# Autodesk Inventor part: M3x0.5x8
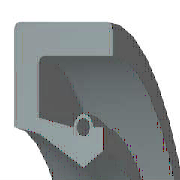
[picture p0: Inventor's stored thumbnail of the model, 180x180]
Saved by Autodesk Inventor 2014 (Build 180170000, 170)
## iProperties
Company: 한국ATC센터
IsCustomPart: 1
Created: 2009-02
Part Number: M3x0.5x8
Material: 고무
Description: 오일-실
Document SubType Name: Modeling
Standard: KS B 2804
Designer: KYOUNG IL JANG
Standards Organization: KS
Language: ko-KR
Size Designation: S - 12 22 7
Categories: <MemberInstance><Categories><Category DisplayName="샤프트 부품" InternalName="7f7aeb1f-a693-4053-b835-cee3144e0d98" Mnemonic="SHFT"><Category DisplayName="실링" Intern
Density: 0.93 g/cm^3
Mass: 1.0258 g
Surface Area: 17.5559 cm^2
Volume: 1.10301 cm^3
Vendor: CBT Solutions
Appearance: 고무 - 검은색 - 버전 1.1
Author: KYOUNG IL JANG
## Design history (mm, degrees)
revolve "본체" stored, may be unused: angle "d17" = 90 deg
revolve "스프링1" stored, may be unused: angle "d18" = 90 deg
body "Solid1"
sketch "스케치1"
  geometry: L1 (0, 11)-(7, 11); L2 (7, 11)-(7, 9.75); L3 (7, 9.75)-(1.75, 9.75); L4 (0, 11)-(0, 8.1); L5 (0, 8.1)-(1.75, 7.75); L6 (1.75, 7.75)-(4.9, 6); L7 (4.9, 6)-(0, 6); L8 (6.3, 6.875)-(6.3, 8.1); L9 (0, 0)-(9.586, 0) reference; L10 (4.9, 6)-(6.3, 6.875); L11 (0, 18)-(0, -3) reference; L12 (-1.917, 0)-(11.503, 0) reference; L13 (4.2, 8.1)-(1.75, 8.59); L14 (1.75, 8.59)-(1.75, 9.75); L15 (6.3, 8.1)-(5.6, 8.1); C1 r 0.455 at (4.9, 8.1); A1 r 0.7 centre (4.9, 8.1) between (5.6, 8.1) and (4.2, 8.1)
  constraints: 26 end point, 5 horizontal alignment, 4 perpendicular, 2 centre point, 2 collinear, 2 horizontal, 2 parallel, 2 point on circle, 2 point on line, 2 vertical alignment, 1 coincident
  dimensions: "d0" = 22 diameter of L1 L9 (= SD2); "d1" = 13.75 diameter of L8.start L9 (= ABDM); "d2" = 1.25 distance of L1.end L2.end (computed from SD); "d3" = 0.91 diameter of C1 (= SPDI); "d4" = 1.4 diameter of A1 (= SPDA); "d5" = 12 diameter of L6.end L9 (= NND); "d6" = 15.5 diameter of L5.end L9 (= TKDM); "d7" = 16.2 diameter of L4.end L9 (= HLDM); "d8" = 4.9 distance from line of C1.centre L4 (= SPDST); "d9" = 6.3 distance between parallel lines of L8 L4 (= SDI); "d10" = 7 distance between parallel lines of L2 L4 (= SWDT); "d12" = 1.75 distance between parallel lines of L14 L4 (= SD)
fillet "모깎기1" dims "d11" = 0.3 (= RR)
other parameters: "SD2" = 22 [user parameter; used in 1 equation term], "SWDT" = 7 [user parameter; used in 1 equation term], "RR" = 0.3 [user parameter; used in 1 equation term], "SD" = 1.75 [user parameter; used in 2 equation terms], "NND" = 12 [user parameter; used in 1 equation term], "SPDA" = 1.4 [user parameter; used in 1 equation term], "SPDI" = 0.91 [user parameter; used in 1 equation term], "TKDM" = 15.5 [user parameter; used in 1 equation term], "HLDM" = 16.2 [user parameter; used in 1 equation term], "ABDM" = 13.75 [user parameter; used in 1 equation term], "SDI" = 6.3 [user parameter; used in 1 equation term], "SPDST" = 4.9 [user parameter; used in 1 equation term], "d13" = 0, "d14" = 0, "d15" = 0, "LAB" = 0.35 [user parameter]
